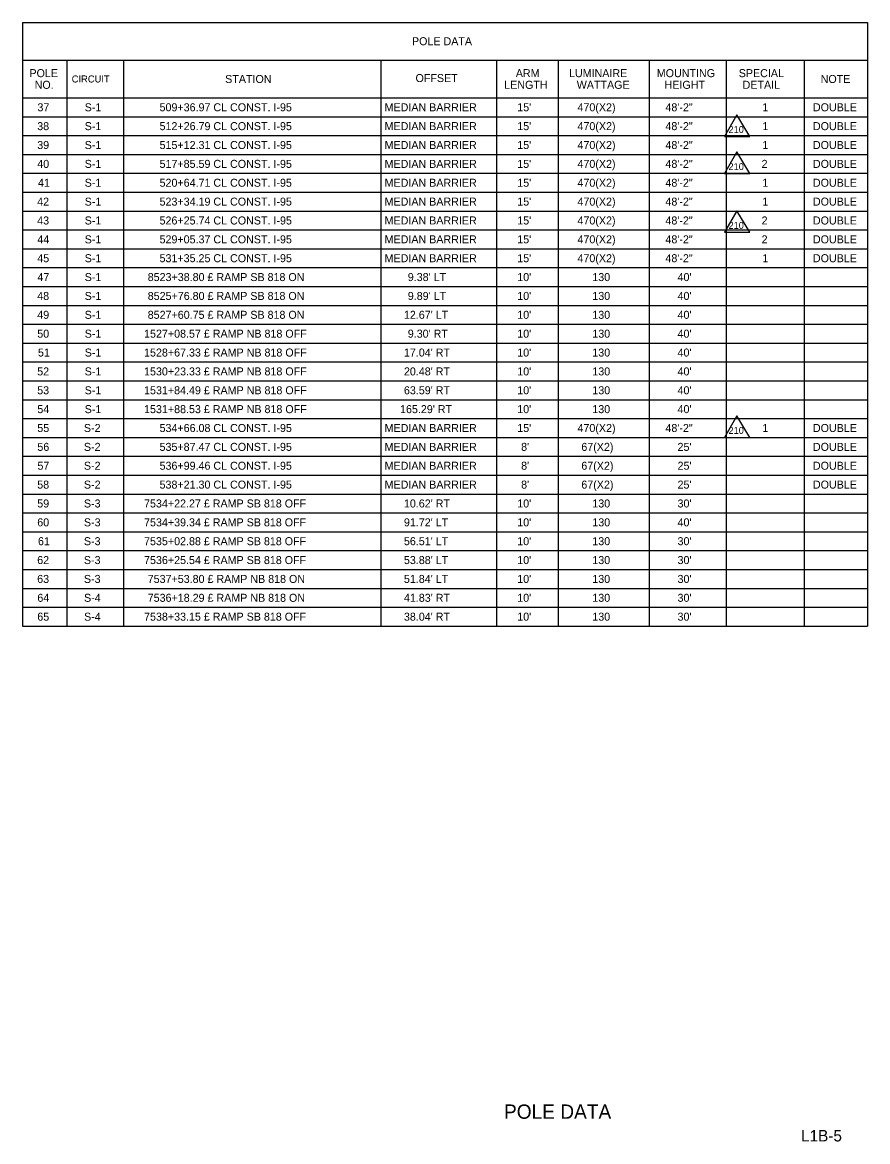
# Model space of a CAD drawing. Extents: x -816.7 to -800.7, y -2197.9 to -2187.9.
# Drawn here: x -808.09 to -800.7, y -2197.64 to -2187.86 of the extents above; entities that cross this region are included whole.
import ezdxf

# ---------------------------------------------------------------- set-up
doc = ezdxf.new("R2010")
doc.units = 0
for name, color, linetype in [('ScratchEle_dp', 7, 'Continuous'), ('SumBoxBorder_dp', 7, 'Continuous'), ('SumBoxLines_dp', 7, 'Continuous'), ('SumBoxLinesMin_dp', 7, 'Continuous'), ('TextLabel', 7, 'Continuous'), ('TextMisc', 7, 'Continuous'), ('TextShtNo', 7, 'Continuous')]:
    doc.layers.add(name, color=color, linetype=linetype)

msp = doc.modelspace()

# ---------------------------------------------------------------- linework, layer by layer
at = {"layer": 'ScratchEle_dp'}
for points in [[(-801.8411, -2188.6653), (-801.9488, -2188.8534), (-801.7282, -2188.8534)], [(-801.8411, -2188.9897), (-801.9488, -2189.1778), (-801.7282, -2189.1778)], [(-801.8411, -2189.504), (-801.9488, -2189.6921), (-801.7282, -2189.6921)], [(-801.8411, -2191.2972), (-801.9488, -2191.4853), (-801.7282, -2191.4853)]]:
    msp.add_lwpolyline(points, close=True, dxfattribs=at)
at = {"layer": 'SumBoxBorder_dp'}
for p, q in [((-808.0923, -2187.8562), (-800.6973, -2187.8562)), ((-808.0923, -2187.8562), (-808.0923, -2193.1362)), ((-800.6973, -2187.8562), (-800.6973, -2193.1362)), ((-808.0923, -2188.1862), (-800.6973, -2188.1862)), ((-808.0923, -2188.1862), (-800.6973, -2188.1862)), ((-808.0923, -2193.1362), (-800.6973, -2193.1362)), ((-808.0923, -2193.1362), (-800.6973, -2193.1362))]:
    msp.add_line(p, q, dxfattribs=at)
at = {"layer": 'SumBoxLines_dp'}
for p, q in [((-807.7023, -2188.1862), (-807.7023, -2193.1362)), ((-807.7023, -2188.1862), (-807.7023, -2193.1362)), ((-807.2073, -2188.1862), (-807.2073, -2191.9812)), ((-807.2073, -2188.1862), (-807.2073, -2193.1362)), ((-804.9573, -2188.1862), (-804.9573, -2191.4862)), ((-804.9573, -2188.1862), (-804.9573, -2193.1362)), ((-803.9448, -2188.1862), (-803.9448, -2193.1362)), ((-803.9448, -2188.1862), (-803.9448, -2193.1362)), ((-803.4048, -2188.1862), (-803.4048, -2191.9812)), ((-803.4048, -2188.1862), (-803.4048, -2193.1362)), ((-802.6098, -2188.1862), (-802.6098, -2193.1362)), ((-802.6098, -2188.1862), (-802.6098, -2193.1362)), ((-801.9348, -2188.1862), (-801.9348, -2193.1362)), ((-801.9348, -2188.1862), (-801.9348, -2193.1362)), ((-801.2523, -2188.1862), (-801.2523, -2193.1362)), ((-808.0923, -2188.5162), (-800.6973, -2188.5162)), ((-804.9573, -2191.6512), (-804.9573, -2193.1362)), ((-807.2073, -2192.1462), (-807.2073, -2192.3112)), ((-803.4048, -2192.1462), (-803.4048, -2193.1362)), ((-807.2073, -2192.4762), (-807.2073, -2192.6412)), ((-807.2073, -2192.8062), (-807.2073, -2193.1362))]:
    msp.add_line(p, q, dxfattribs=at)
at = {"layer": 'SumBoxLinesMin_dp'}
for p, q in [((-808.0923, -2188.5162), (-800.6973, -2188.5162)), ((-808.0923, -2188.6812), (-800.6973, -2188.6812)), ((-808.0923, -2188.6812), (-800.6973, -2188.6812)), ((-808.0923, -2188.8462), (-800.6973, -2188.8462)), ((-808.0923, -2188.8462), (-800.6973, -2188.8462)), ((-808.0923, -2189.0112), (-800.6973, -2189.0112)), ((-808.0923, -2189.0112), (-800.6973, -2189.0112)), ((-808.0923, -2189.1762), (-800.6973, -2189.1762)), ((-808.0923, -2189.1762), (-800.6973, -2189.1762)), ((-808.0923, -2189.3412), (-800.6973, -2189.3412)), ((-808.0923, -2189.3412), (-800.6973, -2189.3412)), ((-808.0923, -2189.5062), (-800.6973, -2189.5062)), ((-808.0923, -2189.5062), (-800.6973, -2189.5062)), ((-808.0923, -2189.6712), (-800.6973, -2189.6712)), ((-808.0923, -2189.6712), (-800.6973, -2189.6712)), ((-808.0923, -2189.8362), (-800.6973, -2189.8362)), ((-808.0923, -2189.8362), (-800.6973, -2189.8362)), ((-808.0923, -2190.0012), (-800.6973, -2190.0012)), ((-808.0923, -2190.0012), (-800.6973, -2190.0012)), ((-808.0923, -2190.1662), (-800.6973, -2190.1662)), ((-808.0923, -2190.1662), (-800.6973, -2190.1662)), ((-808.0923, -2190.3312), (-800.6973, -2190.3312)), ((-808.0923, -2190.3312), (-800.6973, -2190.3312)), ((-808.0923, -2190.4962), (-800.6973, -2190.4962)), ((-808.0923, -2190.4962), (-800.6973, -2190.4962)), ((-808.0923, -2190.6612), (-800.6973, -2190.6612)), ((-808.0923, -2190.6612), (-800.6973, -2190.6612)), ((-808.0923, -2190.8262), (-800.6973, -2190.8262)), ((-808.0923, -2190.8262), (-800.6973, -2190.8262)), ((-808.0923, -2190.9912), (-800.6973, -2190.9912)), ((-808.0923, -2190.9912), (-800.6973, -2190.9912)), ((-808.0923, -2191.1562), (-800.6973, -2191.1562)), ((-808.0923, -2191.1562), (-800.6973, -2191.1562)), ((-808.0923, -2191.3212), (-800.6973, -2191.3212)), ((-808.0923, -2191.3212), (-800.6973, -2191.3212)), ((-808.0923, -2191.4862), (-800.6973, -2191.4862)), ((-808.0923, -2191.4862), (-800.6973, -2191.4862)), ((-808.0923, -2191.6512), (-807.2073, -2191.6512)), ((-808.0923, -2191.6512), (-800.6973, -2191.6512)), ((-804.9573, -2191.6512), (-800.6973, -2191.6512)), ((-808.0923, -2191.8162), (-800.6973, -2191.8162)), ((-808.0923, -2191.8162), (-800.6973, -2191.8162)), ((-808.0923, -2191.9812), (-800.6973, -2191.9812)), ((-808.0923, -2191.9812), (-800.6973, -2191.9812)), ((-808.0923, -2192.1462), (-807.7023, -2192.1462)), ((-808.0923, -2192.1462), (-800.6973, -2192.1462)), ((-807.2073, -2192.1462), (-803.9448, -2192.1462)), ((-803.4048, -2192.1462), (-800.6973, -2192.1462)), ((-808.0923, -2192.3112), (-800.6973, -2192.3112)), ((-808.0923, -2192.3112), (-800.6973, -2192.3112)), ((-808.0923, -2192.4762), (-807.7023, -2192.4762)), ((-808.0923, -2192.4762), (-800.6973, -2192.4762)), ((-804.9573, -2192.4762), (-800.6973, -2192.4762)), ((-808.0923, -2192.6412), (-800.6973, -2192.6412)), ((-808.0923, -2192.6412), (-800.6973, -2192.6412)), ((-808.0923, -2192.8062), (-807.7023, -2192.8062)), ((-808.0923, -2192.8062), (-800.6973, -2192.8062)), ((-804.9573, -2192.8062), (-800.6973, -2192.8062)), ((-808.0923, -2192.9712), (-800.6973, -2192.9712)), ((-808.0923, -2192.9712), (-800.6973, -2192.9712))]:
    msp.add_line(p, q, dxfattribs=at)

# ---------------------------------------------------------------- texts
at = {"layer": 'ScratchEle_dp'}
for p in [(-801.9143, -2188.8232), (-801.9143, -2189.1477), (-801.9143, -2189.6619), (-801.9143, -2191.4552)]:
    msp.add_text('210', height=0.05998, rotation=0, dxfattribs=at).set_placement(p)
at = {"layer": 'TextLabel'}
for s, height, p in [('POLE DATA', 0.07, (-804.6838, -2188.0562)), ('POLE', 0.07, (-808.0306, -2188.3352)), ('CIRCUIT', 0.06125, (-807.6608, -2188.3818)), ('STATION', 0.07, (-806.3182, -2188.3862)), ('OFFSET', 0.07, (-804.6526, -2188.3782)), ('ARM', 0.07, (-803.7754, -2188.3352)), ('LUMINAIRE', 0.07, (-803.31, -2188.3352)), ('MOUNTING', 0.07, (-802.542, -2188.3352)), ('SPECIAL', 0.07, (-801.825, -2188.3352)), ('NOTE', 0.07, (-801.1081, -2188.3862)), ('NO.', 0.07, (-807.985, -2188.4372)), ('LENGTH', 0.07, (-803.8768, -2188.4372)), ('WATTAGE', 0.07, (-803.2423, -2188.4372)), ('HEIGHT', 0.07, (-802.4738, -2188.4372)), ('DETAIL', 0.07, (-801.7911, -2188.4372)), ('37', 0.07, (-807.9606, -2188.6337)), ('S-1', 0.07, (-807.5473, -2188.6337)), ('509+36.97 CL CONST. I-95', 0.07, (-806.8921, -2188.6337)), ('MEDIAN BARRIER', 0.07, (-804.9232, -2188.6337)), ("15'", 0.07, (-803.7628, -2188.6337)), ('470(X2)', 0.07, (-803.2358, -2188.6337)), ('48\'-2"', 0.07, (-802.4663, -2188.6337)), ('1', 0.07, (-801.6183, -2188.6337)), ('DOUBLE', 0.07, (-801.1759, -2188.6337)), ('38', 0.07, (-807.9624, -2188.7987)), ('S-1', 0.07, (-807.5473, -2188.7987)), ('512+26.79 CL CONST. I-95', 0.07, (-806.8921, -2188.7987)), ('MEDIAN BARRIER', 0.07, (-804.9232, -2188.7987)), ("15'", 0.07, (-803.7628, -2188.7987)), ('470(X2)', 0.07, (-803.2358, -2188.7987)), ('48\'-2"', 0.07, (-802.4663, -2188.7987)), ('1', 0.07, (-801.6183, -2188.7987)), ('DOUBLE', 0.07, (-801.1759, -2188.7987)), ('39', 0.07, (-807.9622, -2188.9637)), ('S-1', 0.07, (-807.5473, -2188.9637)), ('515+12.31 CL CONST. I-95', 0.07, (-806.8921, -2188.9637)), ('MEDIAN BARRIER', 0.07, (-804.9232, -2188.9637)), ("15'", 0.07, (-803.7628, -2188.9637)), ('470(X2)', 0.07, (-803.2358, -2188.9637)), ('48\'-2"', 0.07, (-802.4663, -2188.9637)), ('1', 0.07, (-801.6183, -2188.9637)), ('DOUBLE', 0.07, (-801.1759, -2188.9637)), ('40', 0.07, (-807.9621, -2189.1287)), ('S-1', 0.07, (-807.5473, -2189.1287)), ('517+85.59 CL CONST. I-95', 0.07, (-806.8921, -2189.1287)), ('MEDIAN BARRIER', 0.07, (-804.9232, -2189.1287)), ("15'", 0.07, (-803.7628, -2189.1287)), ('470(X2)', 0.07, (-803.2358, -2189.1287)), ('48\'-2"', 0.07, (-802.4663, -2189.1287)), ('2', 0.07, (-801.625, -2189.1287)), ('DOUBLE', 0.07, (-801.1759, -2189.1287)), ('41', 0.07, (-807.9559, -2189.2937)), ('S-1', 0.07, (-807.5473, -2189.2937)), ('520+64.71 CL CONST. I-95', 0.07, (-806.8921, -2189.2937)), ('MEDIAN BARRIER', 0.07, (-804.9232, -2189.2937)), ("15'", 0.07, (-803.7628, -2189.2937)), ('470(X2)', 0.07, (-803.2358, -2189.2937)), ('48\'-2"', 0.07, (-802.4663, -2189.2937)), ('1', 0.07, (-801.6183, -2189.2937)), ('DOUBLE', 0.07, (-801.1759, -2189.2937)), ('42', 0.07, (-807.9626, -2189.4587)), ('S-1', 0.07, (-807.5473, -2189.4587)), ('523+34.19 CL CONST. I-95', 0.07, (-806.8921, -2189.4587)), ('MEDIAN BARRIER', 0.07, (-804.9232, -2189.4587)), ("15'", 0.07, (-803.7628, -2189.4587)), ('470(X2)', 0.07, (-803.2358, -2189.4587)), ('48\'-2"', 0.07, (-802.4663, -2189.4587)), ('1', 0.07, (-801.6183, -2189.4587)), ('DOUBLE', 0.07, (-801.1759, -2189.4587)), ('43', 0.07, (-807.9627, -2189.6237)), ('S-1', 0.07, (-807.5473, -2189.6237)), ('526+25.74 CL CONST. I-95', 0.07, (-806.8921, -2189.6237)), ('MEDIAN BARRIER', 0.07, (-804.9232, -2189.6237)), ("15'", 0.07, (-803.7628, -2189.6237)), ('470(X2)', 0.07, (-803.2358, -2189.6237)), ('48\'-2"', 0.07, (-802.4663, -2189.6237)), ('2', 0.07, (-801.625, -2189.6237)), ('DOUBLE', 0.07, (-801.1759, -2189.6237)), ('470(X2)', 0.07, (-803.2358, -2189.7887)), ('44', 0.07, (-807.9613, -2189.7887)), ('S-1', 0.07, (-807.5473, -2189.7887)), ('529+05.37 CL CONST. I-95', 0.07, (-806.8921, -2189.7887)), ('MEDIAN BARRIER', 0.07, (-804.9232, -2189.7887)), ("15'", 0.07, (-803.7628, -2189.7887)), ('48\'-2"', 0.07, (-802.4663, -2189.7887)), ('2', 0.07, (-801.625, -2189.7887)), ('DOUBLE', 0.07, (-801.1759, -2189.7887)), ('45', 0.07, (-807.9618, -2189.9537)), ('S-1', 0.07, (-807.5473, -2189.9537)), ('531+35.25 CL CONST. I-95', 0.07, (-806.8921, -2189.9537)), ('MEDIAN BARRIER', 0.07, (-804.9232, -2189.9537)), ("15'", 0.07, (-803.7628, -2189.9537)), ('470(X2)', 0.07, (-803.2358, -2189.9537)), ('48\'-2"', 0.07, (-802.4663, -2189.9537)), ('1', 0.07, (-801.6183, -2189.9537)), ('DOUBLE', 0.07, (-801.1759, -2189.9537)), ('47', 0.07, (-807.9606, -2190.1187)), ('S-1', 0.07, (-807.5473, -2190.1187)), ('8523+38.80 £ RAMP SB 818 ON', 0.07, (-806.9957, -2190.1187)), ("9.38' LT", 0.07, (-804.7203, -2190.1187)), ("10'", 0.07, (-803.7628, -2190.1187)), ('130', 0.07, (-803.1059, -2190.1187)), ("40'", 0.07, (-802.3603, -2190.1187)), ('48', 0.07, (-807.9624, -2190.2837)), ('S-1', 0.07, (-807.5473, -2190.2837)), ('8525+76.80 £ RAMP SB 818 ON', 0.07, (-806.9957, -2190.2837)), ("9.89' LT", 0.07, (-804.7203, -2190.2837)), ("10'", 0.07, (-803.7628, -2190.2837)), ('130', 0.07, (-803.1059, -2190.2837)), ("40'", 0.07, (-802.3603, -2190.2837)), ('49', 0.07, (-807.9622, -2190.4487)), ('S-1', 0.07, (-807.5473, -2190.4487)), ('8527+60.75 £ RAMP SB 818 ON', 0.07, (-806.9957, -2190.4487)), ("12.67' LT", 0.07, (-804.7542, -2190.4487)), ("10'", 0.07, (-803.7628, -2190.4487)), ('130', 0.07, (-803.1059, -2190.4487)), ("40'", 0.07, (-802.3603, -2190.4487)), ('50', 0.07, (-807.9621, -2190.6137)), ('S-1', 0.07, (-807.5473, -2190.6137)), ('1527+08.57 £ RAMP NB 818 OFF', 0.07, (-807.0277, -2190.6137)), ("9.30' RT", 0.07, (-804.7203, -2190.6137)), ("10'", 0.07, (-803.7628, -2190.6137)), ('130', 0.07, (-803.1059, -2190.6137)), ("40'", 0.07, (-802.3603, -2190.6137)), ('51', 0.07, (-807.9559, -2190.7787)), ('S-1', 0.07, (-807.5473, -2190.7787)), ('1528+67.33 £ RAMP NB 818 OFF', 0.07, (-807.0277, -2190.7787)), ("17.04' RT", 0.07, (-804.7542, -2190.7787)), ("10'", 0.07, (-803.7628, -2190.7787)), ('130', 0.07, (-803.1059, -2190.7787)), ("40'", 0.07, (-802.3603, -2190.7787)), ('52', 0.07, (-807.9626, -2190.9437)), ('S-1', 0.07, (-807.5473, -2190.9437)), ('1530+23.33 £ RAMP NB 818 OFF', 0.07, (-807.0277, -2190.9437)), ("20.48' RT", 0.07, (-804.7542, -2190.9437)), ("10'", 0.07, (-803.7628, -2190.9437)), ('130', 0.07, (-803.1059, -2190.9437)), ("40'", 0.07, (-802.3603, -2190.9437)), ('53', 0.07, (-807.9627, -2191.1087)), ('S-1', 0.07, (-807.5473, -2191.1087)), ('1531+84.49 £ RAMP NB 818 OFF', 0.07, (-807.0277, -2191.1087)), ("63.59' RT", 0.07, (-804.7542, -2191.1087)), ("10'", 0.07, (-803.7628, -2191.1087)), ('130', 0.07, (-803.1059, -2191.1087)), ("40'", 0.07, (-802.3603, -2191.1087)), ('54', 0.07, (-807.9613, -2191.2737)), ('S-1', 0.07, (-807.5473, -2191.2737)), ('1531+88.53 £ RAMP NB 818 OFF', 0.07, (-807.0277, -2191.2737)), ("165.29' RT", 0.07, (-804.7881, -2191.2737)), ("10'", 0.07, (-803.7628, -2191.2737)), ('130', 0.07, (-803.1059, -2191.2737)), ("40'", 0.07, (-802.3603, -2191.2737)), ('55', 0.07, (-807.9618, -2191.4387)), ('S-2', 0.07, (-807.554, -2191.4387)), ('534+66.08 CL CONST. I-95', 0.07, (-806.8921, -2191.4387)), ('MEDIAN BARRIER', 0.07, (-804.9232, -2191.4387)), ("15'", 0.07, (-803.7628, -2191.4387)), ('470(X2)', 0.07, (-803.2358, -2191.4387)), ('48\'-2"', 0.07, (-802.4663, -2191.4387)), ('1', 0.07, (-801.6183, -2191.4387)), ('DOUBLE', 0.07, (-801.1759, -2191.4387)), ('56', 0.07, (-807.9612, -2191.6037)), ('S-2', 0.07, (-807.554, -2191.6037)), ('535+87.47 CL CONST. I-95', 0.07, (-806.8921, -2191.6037)), ('MEDIAN BARRIER', 0.07, (-804.9232, -2191.6037)), ("8'", 0.07, (-803.7289, -2191.6037)), ('67(X2)', 0.07, (-803.202, -2191.6037)), ("25'", 0.07, (-802.3603, -2191.6037)), ('DOUBLE', 0.07, (-801.1759, -2191.6037)), ('57', 0.07, (-807.9606, -2191.7687)), ('S-2', 0.07, (-807.554, -2191.7687)), ('536+99.46 CL CONST. I-95', 0.07, (-806.8921, -2191.7687)), ('MEDIAN BARRIER', 0.07, (-804.9232, -2191.7687)), ("8'", 0.07, (-803.7289, -2191.7687)), ('67(X2)', 0.07, (-803.202, -2191.7687)), ("25'", 0.07, (-802.3603, -2191.7687)), ('DOUBLE', 0.07, (-801.1759, -2191.7687)), ('58', 0.07, (-807.9624, -2191.9337)), ('S-2', 0.07, (-807.554, -2191.9337)), ('538+21.30 CL CONST. I-95', 0.07, (-806.8921, -2191.9337)), ('MEDIAN BARRIER', 0.07, (-804.9232, -2191.9337)), ("8'", 0.07, (-803.7289, -2191.9337)), ('67(X2)', 0.07, (-803.202, -2191.9337)), ("25'", 0.07, (-802.3603, -2191.9337)), ('DOUBLE', 0.07, (-801.1759, -2191.9337)), ('59', 0.07, (-807.9622, -2192.0987)), ('S-3', 0.07, (-807.554, -2192.0987)), ('7534+22.27 £ RAMP SB 818 OFF', 0.07, (-807.0277, -2192.0987)), ("10.62' RT", 0.07, (-804.7542, -2192.0987)), ("10'", 0.07, (-803.7628, -2192.0987)), ('130', 0.07, (-803.1059, -2192.0987)), ("30'", 0.07, (-802.3603, -2192.0987)), ('60', 0.07, (-807.9621, -2192.2637)), ('S-3', 0.07, (-807.554, -2192.2637)), ('7534+39.34 £ RAMP SB 818 OFF', 0.07, (-807.0277, -2192.2637)), ("91.72' LT", 0.07, (-804.7542, -2192.2637)), ("10'", 0.07, (-803.7628, -2192.2637)), ('130', 0.07, (-803.1059, -2192.2637)), ("40'", 0.07, (-802.3603, -2192.2637)), ('61', 0.07, (-807.9559, -2192.4287)), ('S-3', 0.07, (-807.554, -2192.4287)), ('7535+02.88 £ RAMP SB 818 OFF', 0.07, (-807.0277, -2192.4287)), ("56.51' LT", 0.07, (-804.7542, -2192.4287)), ("10'", 0.07, (-803.7628, -2192.4287)), ('130', 0.07, (-803.1059, -2192.4287)), ("30'", 0.07, (-802.3603, -2192.4287)), ('62', 0.07, (-807.9626, -2192.5937)), ('S-3', 0.07, (-807.554, -2192.5937)), ('7536+25.54 £ RAMP SB 818 OFF', 0.07, (-807.0277, -2192.5937)), ("53.88' LT", 0.07, (-804.7542, -2192.5937)), ("10'", 0.07, (-803.7628, -2192.5937)), ('130', 0.07, (-803.1059, -2192.5937)), ("30'", 0.07, (-802.3603, -2192.5937)), ('63', 0.07, (-807.9627, -2192.7587)), ('S-3', 0.07, (-807.554, -2192.7587)), ('7537+53.80 £ RAMP NB 818 ON', 0.07, (-806.9957, -2192.7587)), ("51.84' LT", 0.07, (-804.7542, -2192.7587)), ("10'", 0.07, (-803.7628, -2192.7587)), ('130', 0.07, (-803.1059, -2192.7587)), ("30'", 0.07, (-802.3603, -2192.7587)), ('64', 0.07, (-807.9613, -2192.9237)), ('S-4', 0.07, (-807.5526, -2192.9237)), ('7536+18.29 £ RAMP NB 818 ON', 0.07, (-806.9957, -2192.9237)), ("41.83' RT", 0.07, (-804.7542, -2192.9237)), ("10'", 0.07, (-803.7628, -2192.9237)), ('130', 0.07, (-803.1059, -2192.9237)), ("30'", 0.07, (-802.3603, -2192.9237)), ('65', 0.07, (-807.9618, -2193.0887)), ('S-4', 0.07, (-807.5526, -2193.0887)), ('7538+33.15 £ RAMP SB 818 OFF', 0.07, (-807.0277, -2193.0887)), ("38.04' RT", 0.07, (-804.7542, -2193.0887)), ("10'", 0.07, (-803.7628, -2193.0887)), ('130', 0.07, (-803.1059, -2193.0887)), ("30'", 0.07, (-802.3603, -2193.0887))]:
    msp.add_text(s, height=height, dxfattribs=at).set_placement(p)
at = {"layer": 'TextMisc'}
msp.add_text('POLE DATA', height=0.125, dxfattribs=at).set_placement((-803.8787, -2197.445))
at = {"layer": 'TextShtNo'}
msp.add_text('L1B-5  ', height=0.1, dxfattribs=at).set_placement((-801.2789, -2197.6434))

doc.saveas('drawing.dxf')
